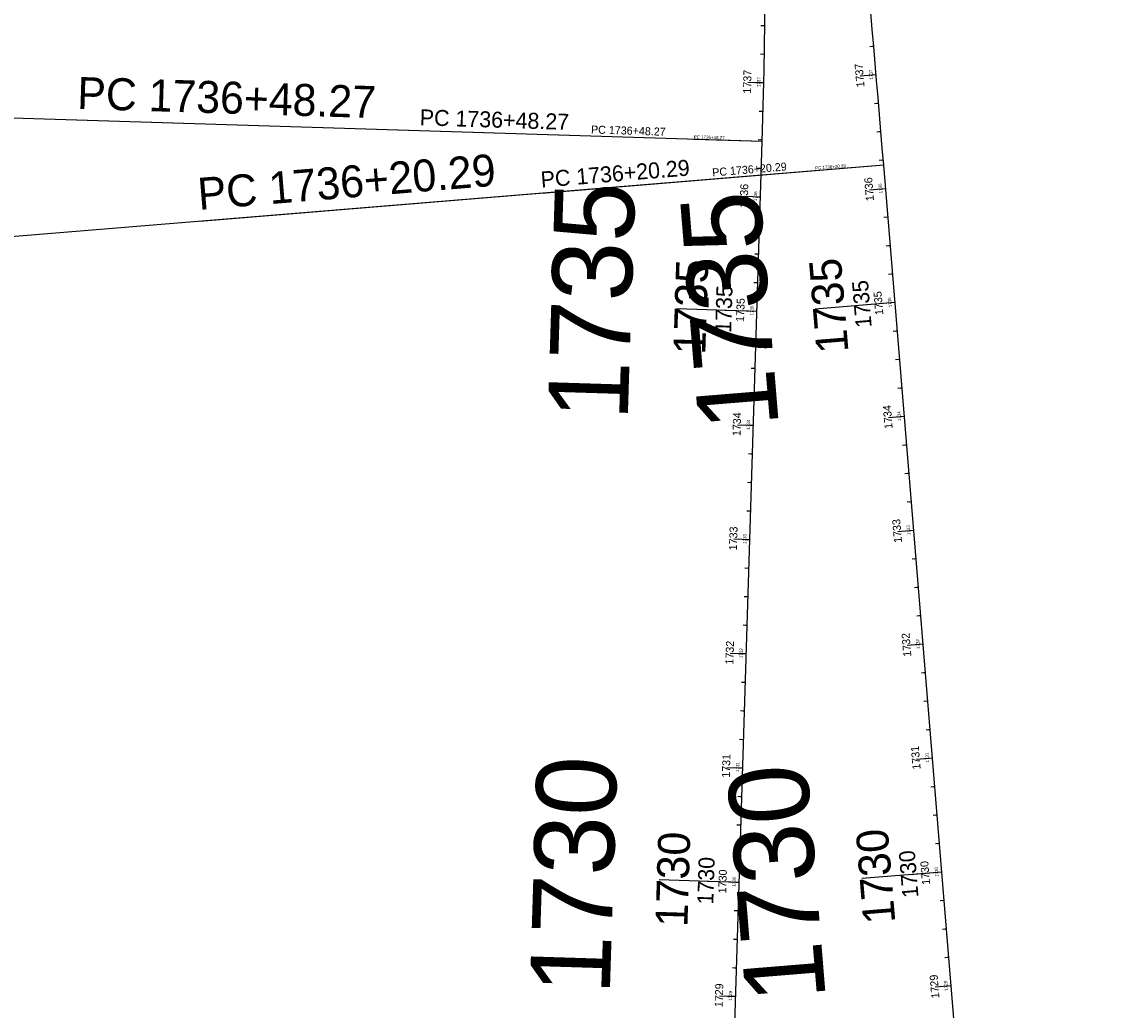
# Model space of a CAD drawing. Extents: x 353835 to 363333, y 126218 to 205387.
# Drawn here: x 360814 to 361763, y 132088 to 132953 of the extents above; entities that cross this region are included whole.
import ezdxf

# ---------------------------------------------------------------- set-up
doc = ezdxf.new("R2010")
doc.units = 0
for name, color, linetype in [('P_ALI_100_PIData', 7, 'Continuous'), ('P_ALI_100_Sta', 7, 'Continuous'), ('P_ALI_100_Tic', 7, 'Continuous'), ('P_ALI_20', 7, 'Continuous'), ('P_ALI_200_PIData', 7, 'Continuous'), ('P_ALI_200_Sta', 7, 'Continuous'), ('P_ALI_200_Tic', 7, 'Continuous'), ('P_ALI_20_PIData', 7, 'Continuous'), ('P_ALI_20_Sta', 7, 'Continuous'), ('P_ALI_20_Tic', 7, 'Continuous'), ('P_ALI_500_PIData', 7, 'Continuous'), ('P_ALI_500_Sta', 7, 'Continuous'), ('P_ALI_50_PIData', 7, 'Continuous'), ('P_ALI_50_Sta', 7, 'Continuous'), ('P_ALI_50_Tic', 7, 'Continuous')]:
    doc.layers.add(name, color=color, linetype=linetype)

msp = doc.modelspace()

# ---------------------------------------------------------------- linework, layer by layer
for points in [[(361561.59, 132906.59), (361561.61, 132906.59)], [(361569.89, 132806.93), (361569.91, 132806.93)], [(361586.24, 132607.6), (361586.26, 132607.6)], [(361594.42, 132507.94), (361594.44, 132507.94)], [(361602.59, 132408.27), (361602.61, 132408.27)], [(361610.77, 132308.61), (361610.79, 132308.61)], [(361627.12, 132109.28), (361627.14, 132109.28)]]:
    msp.add_lwpolyline(points)
at = {"layer": 'P_ALI_100_PIData'}
for points in [[(361462, 132847.85), (361162.15, 132857.21)], [(361462, 132847.85), (361402.03, 132849.72)], [(361568.24, 132827.16), (361269.24, 132802.63)], [(361568.24, 132827.16), (361508.44, 132822.25)]]:
    msp.add_lwpolyline(points, dxfattribs=at)
at = {"layer": 'P_ALI_100_Tic'}
for points in [[(361456.39, 132899.72), (361463.39, 132899.56)], [(361554.62, 132905.99), (361561.6, 132906.59)], [(361562.92, 132806.36), (361569.9, 132806.93)], [(361453.5, 132799.82), (361460.5, 132799.6)], [(361387.41, 132701.83), (361457.38, 132699.65)], [(361443.39, 132700.09), (361457.38, 132699.65)], [(361508.31, 132701.54), (361578.07, 132707.27)], [(361564.12, 132706.12), (361578.07, 132707.27)], [(361579.27, 132607.03), (361586.25, 132607.6)], [(361447.26, 132599.92), (361454.26, 132599.7)], [(361587.45, 132507.36), (361594.43, 132507.94)], [(361444.14, 132499.97), (361451.14, 132499.75)], [(361595.63, 132407.7), (361602.6, 132408.27)], [(361441.02, 132400.01), (361448.02, 132399.8)], [(361603.8, 132308.03), (361610.78, 132308.61)], [(361437.9, 132300.06), (361444.9, 132299.84)], [(361549.19, 132203.22), (361618.95, 132208.94)], [(361605, 132207.8), (361618.95, 132208.94)], [(361371.81, 132202.08), (361441.78, 132199.89)], [(361427.79, 132200.33), (361441.78, 132199.89)], [(361620.15, 132108.7), (361627.13, 132109.28)], [(361431.66, 132100.16), (361438.66, 132099.94)]]:
    msp.add_lwpolyline(points, dxfattribs=at)
at = {"layer": 'P_ALI_20'}
for p, q in [((361371.19, 129938.32), (361462, 132847.85)), ((361762.92, 130454.08), (361568.24, 132827.16))]:
    msp.add_line(p, q, dxfattribs=at)
for centre, radius, start, end in [((355564.88, 133031.92), 5900, 358.212155, 4.675416), ((336651.94, 130783.14), 25000, 4.689776, 5.78337)]:
    msp.add_arc(centre, radius, start, end, dxfattribs=at)
at = {"layer": 'P_ALI_200_PIData'}
for points in [[(361462, 132847.85), (360862.3, 132866.57)], [(361568.24, 132827.16), (360970.25, 132778.1)]]:
    msp.add_lwpolyline(points, dxfattribs=at)
at = {"layer": 'P_ALI_200_Tic'}
for points in [[(361449.4, 132899.87), (361463.39, 132899.56)], [(361547.65, 132905.4), (361561.6, 132906.59)], [(361555.94, 132805.79), (361569.9, 132806.93)], [(361446.51, 132800.04), (361460.5, 132799.6)], [(361429.39, 132700.52), (361457.38, 132699.65)], [(361550.17, 132704.98), (361578.07, 132707.27)], [(361572.3, 132606.46), (361586.25, 132607.6)], [(361440.27, 132600.14), (361454.26, 132599.7)], [(361437.15, 132500.18), (361451.14, 132499.75)], [(361580.47, 132506.79), (361594.43, 132507.94)], [(361588.65, 132407.13), (361602.6, 132408.27)], [(361434.03, 132400.23), (361448.02, 132399.8)], [(361596.83, 132307.46), (361610.78, 132308.61)], [(361430.91, 132300.28), (361444.9, 132299.84)], [(361591.05, 132206.65), (361618.95, 132208.94)], [(361413.79, 132200.77), (361441.78, 132199.89)], [(361613.18, 132108.13), (361627.13, 132109.28)], [(361424.67, 132100.38), (361438.66, 132099.94)]]:
    msp.add_lwpolyline(points, dxfattribs=at)
at = {"layer": 'P_ALI_20_Tic'}
for points in [[(361462.9, 132949.57), (361464.3, 132949.55)], [(361558.06, 132931.38), (361559.46, 132931.5)], [(361462.5, 132924.58), (361463.9, 132924.55)], [(361460.59, 132899.62), (361463.39, 132899.56)], [(361558.81, 132906.35), (361561.6, 132906.59)], [(361562.31, 132881.56), (361563.71, 132881.68)], [(361461.38, 132874.6), (361462.78, 132874.57)], [(361564.4, 132856.65), (361565.79, 132856.76)], [(361460.66, 132849.62), (361462.06, 132849.58)], [(361459.88, 132824.63), (361461.28, 132824.59)], [(361566.46, 132831.73), (361567.85, 132831.85)], [(361567.11, 132806.7), (361569.9, 132806.93)], [(361457.7, 132799.69), (361460.5, 132799.6)], [(361570.55, 132781.9), (361571.94, 132782.02)], [(361458.32, 132774.66), (361459.72, 132774.61)], [(361572.59, 132756.99), (361573.99, 132757.1)], [(361457.54, 132749.67), (361458.94, 132749.63)], [(361574.63, 132732.07), (361576.03, 132732.18)], [(361456.76, 132724.68), (361458.16, 132724.64)], [(361454.58, 132699.74), (361457.38, 132699.65)], [(361575.28, 132707.04), (361578.07, 132707.27)], [(361578.72, 132682.24), (361580.12, 132682.35)], [(361455.2, 132674.71), (361456.6, 132674.66)], [(361580.77, 132657.32), (361582.16, 132657.43)], [(361454.42, 132649.72), (361455.82, 132649.67)], [(361453.64, 132624.73), (361455.04, 132624.69)], [(361582.81, 132632.4), (361584.21, 132632.52)], [(361583.46, 132607.37), (361586.25, 132607.6)], [(361451.46, 132599.79), (361454.26, 132599.7)], [(361586.9, 132582.57), (361588.29, 132582.69)], [(361452.08, 132574.75), (361453.48, 132574.71)], [(361588.94, 132557.66), (361590.34, 132557.77)], [(361451.3, 132549.77), (361452.7, 132549.72)], [(361590.99, 132532.74), (361592.38, 132532.85)], [(361450.52, 132524.78), (361451.92, 132524.74)], [(361591.64, 132507.71), (361594.43, 132507.94)], [(361448.34, 132499.83), (361451.14, 132499.75)], [(361595.07, 132482.91), (361596.47, 132483.02)], [(361448.96, 132474.8), (361450.36, 132474.76)], [(361597.12, 132457.99), (361598.51, 132458.1)], [(361448.18, 132449.82), (361449.58, 132449.77)], [(361447.4, 132424.83), (361448.8, 132424.78)], [(361599.16, 132433.07), (361600.56, 132433.19)], [(361599.81, 132408.04), (361602.6, 132408.27)], [(361445.22, 132399.88), (361448.02, 132399.8)], [(361603.25, 132383.24), (361604.65, 132383.36)], [(361445.84, 132374.85), (361447.24, 132374.81)], [(361605.3, 132358.32), (361606.69, 132358.44)], [(361445.06, 132349.86), (361446.46, 132349.82)], [(361607.34, 132333.41), (361608.73, 132333.52)], [(361444.28, 132324.88), (361445.68, 132324.83)], [(361607.99, 132308.38), (361610.78, 132308.61)], [(361442.1, 132299.93), (361444.9, 132299.84)], [(361611.43, 132283.58), (361612.82, 132283.69)], [(361442.72, 132274.9), (361444.12, 132274.86)], [(361613.47, 132258.66), (361614.87, 132258.77)], [(361441.94, 132249.91), (361443.34, 132249.87)], [(361441.16, 132224.92), (361442.56, 132224.88)], [(361615.52, 132233.74), (361616.91, 132233.86)], [(361616.16, 132208.71), (361618.95, 132208.94)], [(361438.98, 132199.98), (361441.78, 132199.89)], [(361619.6, 132183.91), (361621, 132184.03)], [(361439.6, 132174.95), (361441, 132174.91)], [(361621.65, 132158.99), (361623.04, 132159.11)], [(361438.82, 132149.96), (361440.22, 132149.92)], [(361623.69, 132134.08), (361625.09, 132134.19)], [(361438.04, 132124.97), (361439.44, 132124.93)], [(361624.34, 132109.05), (361627.13, 132109.28)], [(361435.86, 132100.03), (361438.66, 132099.94)]]:
    msp.add_lwpolyline(points, dxfattribs=at)
at = {"layer": 'P_ALI_500_PIData'}
for points in [[(361462, 132847.85), (359962.74, 132894.64)], [(361568.24, 132827.16), (360073.26, 132704.51)]]:
    msp.add_lwpolyline(points, dxfattribs=at)
at = {"layer": 'P_ALI_50_PIData'}
for points in [[(361462, 132847.85), (361312.08, 132852.53)], [(361462, 132847.85), (361312.08, 132852.53)], [(361568.24, 132827.16), (361418.74, 132814.89)]]:
    msp.add_lwpolyline(points, dxfattribs=at)
at = {"layer": 'P_ALI_50_Tic'}
for points in [[(361460.8, 132949.6), (361464.3, 132949.55)], [(361460.8, 132949.6), (361464.3, 132949.55)], [(361555.97, 132931.2), (361559.46, 132931.5)], [(361460.4, 132924.62), (361463.9, 132924.55)], [(361460.4, 132924.62), (361463.9, 132924.55)], [(361456.39, 132899.72), (361463.39, 132899.56)], [(361456.39, 132899.72), (361463.39, 132899.56)], [(361554.62, 132905.99), (361561.6, 132906.59)], [(361560.22, 132881.38), (361563.71, 132881.68)], [(361459.28, 132874.66), (361462.78, 132874.57)], [(361459.28, 132874.66), (361462.78, 132874.57)], [(361562.3, 132856.47), (361565.79, 132856.76)], [(361458.56, 132849.69), (361462.06, 132849.58)], [(361458.56, 132849.69), (361462.06, 132849.58)], [(361457.78, 132824.7), (361461.28, 132824.59)], [(361457.78, 132824.7), (361461.28, 132824.59)], [(361564.37, 132831.56), (361567.85, 132831.85)], [(361562.92, 132806.36), (361569.9, 132806.93)], [(361453.5, 132799.82), (361460.5, 132799.6)], [(361453.5, 132799.82), (361460.5, 132799.6)], [(361568.45, 132781.73), (361571.94, 132782.02)], [(361456.22, 132774.72), (361459.72, 132774.61)], [(361456.22, 132774.72), (361459.72, 132774.61)], [(361570.5, 132756.81), (361573.99, 132757.1)], [(361455.44, 132749.73), (361458.94, 132749.63)], [(361455.44, 132749.73), (361458.94, 132749.63)], [(361572.54, 132731.9), (361576.03, 132732.18)], [(361454.66, 132724.75), (361458.16, 132724.64)], [(361454.66, 132724.75), (361458.16, 132724.64)], [(361450.38, 132699.87), (361457.38, 132699.65)], [(361450.38, 132699.87), (361457.38, 132699.65)], [(361571.1, 132706.7), (361578.07, 132707.27)], [(361576.63, 132682.07), (361580.12, 132682.35)], [(361453.1, 132674.77), (361456.6, 132674.66)], [(361453.1, 132674.77), (361456.6, 132674.66)], [(361578.67, 132657.15), (361582.16, 132657.43)], [(361452.32, 132649.78), (361455.82, 132649.67)], [(361452.32, 132649.78), (361455.82, 132649.67)], [(361451.54, 132624.8), (361455.04, 132624.69)], [(361451.54, 132624.8), (361455.04, 132624.69)], [(361580.72, 132632.23), (361584.21, 132632.52)], [(361579.27, 132607.03), (361586.25, 132607.6)], [(361447.26, 132599.92), (361454.26, 132599.7)], [(361447.26, 132599.92), (361454.26, 132599.7)], [(361584.81, 132582.4), (361588.29, 132582.69)], [(361449.98, 132574.82), (361453.48, 132574.71)], [(361449.98, 132574.82), (361453.48, 132574.71)], [(361586.85, 132557.48), (361590.34, 132557.77)], [(361449.2, 132549.83), (361452.7, 132549.72)], [(361449.2, 132549.83), (361452.7, 132549.72)], [(361588.89, 132532.57), (361592.38, 132532.85)], [(361448.42, 132524.84), (361451.92, 132524.74)], [(361448.42, 132524.84), (361451.92, 132524.74)], [(361587.45, 132507.36), (361594.43, 132507.94)], [(361444.14, 132499.97), (361451.14, 132499.75)], [(361444.14, 132499.97), (361451.14, 132499.75)], [(361592.98, 132482.73), (361596.47, 132483.02)], [(361446.86, 132474.87), (361450.36, 132474.76)], [(361446.86, 132474.87), (361450.36, 132474.76)], [(361595.03, 132457.82), (361598.51, 132458.1)], [(361446.08, 132449.88), (361449.58, 132449.77)], [(361446.08, 132449.88), (361449.58, 132449.77)], [(361445.3, 132424.89), (361448.8, 132424.78)], [(361445.3, 132424.89), (361448.8, 132424.78)], [(361597.07, 132432.9), (361600.56, 132433.19)], [(361595.63, 132407.7), (361602.6, 132408.27)], [(361441.02, 132400.01), (361448.02, 132399.8)], [(361441.02, 132400.01), (361448.02, 132399.8)], [(361601.16, 132383.07), (361604.65, 132383.36)], [(361443.74, 132374.92), (361447.24, 132374.81)], [(361443.74, 132374.92), (361447.24, 132374.81)], [(361603.2, 132358.15), (361606.69, 132358.44)], [(361442.96, 132349.93), (361446.46, 132349.82)], [(361442.96, 132349.93), (361446.46, 132349.82)], [(361605.25, 132333.24), (361608.73, 132333.52)], [(361442.18, 132324.94), (361445.68, 132324.83)], [(361442.18, 132324.94), (361445.68, 132324.83)], [(361603.8, 132308.03), (361610.78, 132308.61)], [(361437.9, 132300.06), (361444.9, 132299.84)], [(361437.9, 132300.06), (361444.9, 132299.84)], [(361609.33, 132283.4), (361612.82, 132283.69)], [(361440.62, 132274.97), (361444.12, 132274.86)], [(361440.62, 132274.97), (361444.12, 132274.86)], [(361611.38, 132258.49), (361614.87, 132258.77)], [(361439.84, 132249.98), (361443.34, 132249.87)], [(361439.84, 132249.98), (361443.34, 132249.87)], [(361439.06, 132224.99), (361442.56, 132224.88)], [(361439.06, 132224.99), (361442.56, 132224.88)], [(361613.42, 132233.57), (361616.91, 132233.86)], [(361611.98, 132208.37), (361618.95, 132208.94)], [(361434.78, 132200.11), (361441.78, 132199.89)], [(361434.78, 132200.11), (361441.78, 132199.89)], [(361617.51, 132183.74), (361621, 132184.03)], [(361437.5, 132175.01), (361441, 132174.91)], [(361437.5, 132175.01), (361441, 132174.91)], [(361619.55, 132158.82), (361623.04, 132159.11)], [(361436.72, 132150.03), (361440.22, 132149.92)], [(361436.72, 132150.03), (361440.22, 132149.92)], [(361621.6, 132133.91), (361625.09, 132134.19)], [(361435.94, 132125.04), (361439.44, 132124.93)], [(361435.94, 132125.04), (361439.44, 132124.93)], [(361620.15, 132108.7), (361627.13, 132109.28)], [(361431.66, 132100.16), (361438.66, 132099.94)], [(361431.66, 132100.16), (361438.66, 132099.94)]]:
    msp.add_lwpolyline(points, dxfattribs=at)

# ---------------------------------------------------------------- texts
at = {"layer": 'P_ALI_100_PIData'}
for s, rotation, p in [('PC 1736+48.27', 358.21215, (361162.31, 132862.2)), ('PC 1736+20.29', 4.68978, (361268.83, 132807.61))]:
    msp.add_text(s, height=14, rotation=rotation, dxfattribs=at).set_placement(p)
at = {"layer": 'P_ALI_100_Sta'}
for s, rotation, p in [('1735', 88.21215, (361434.77, 132680.39)), ('1735', 94.68978, (361557.78, 132685.58)), ('1730', 94.68978, (361598.7, 132186.71)), ('1730', 88.21215, (361419.15, 132180.09))]:
    msp.add_text(s, height=14, rotation=rotation, dxfattribs=at).set_placement(p)
at = {"layer": 'P_ALI_200_PIData'}
for s, rotation, p in [('PC 1736+48.27', 358.21215, (360862.61, 132876.56)), ('PC 1736+20.29', 4.68978, (360969.43, 132788.07))]:
    msp.add_text(s, height=28, rotation=rotation, dxfattribs=at).set_placement(p)
at = {"layer": 'P_ALI_200_Sta'}
for s, rotation, p in [('1735', 88.21215, (361412.16, 132661.14)), ('1735', 94.68978, (361537.48, 132663.9)), ('1730', 94.68978, (361578.45, 132164.47)), ('1730', 88.21215, (361396.52, 132160.28))]:
    msp.add_text(s, height=28, rotation=rotation, dxfattribs=at).set_placement(p)
at = {"layer": 'P_ALI_20_PIData'}
for s, rotation, p in [('PC 1736+48.27', 358.21215, (361402.07, 132850.72)), ('PC 1736+20.29', 4.68978, (361508.36, 132823.25)), ('PC 1736+20.29', 4.68978, (361508.36, 132823.25))]:
    msp.add_text(s, height=2.8, rotation=rotation, dxfattribs=at).set_placement(p)
at = {"layer": 'P_ALI_20_Sta'}
for s, rotation, p in [('1737', 94.87246, (361558.87, 132902.35)), ('1737', 88.71453, (361460.22, 132895.64)), ('1736', 88.21215, (361457.3, 132795.72)), ('1736', 94.68978, (361567.15, 132802.71)), ('1735', 94.68978, (361575.33, 132703.04)), ('1735', 88.21215, (361454.18, 132695.76)), ('1734', 94.68978, (361583.51, 132603.37)), ('1734', 88.21215, (361451.06, 132595.81)), ('1733', 94.68978, (361591.68, 132503.71)), ('1733', 88.21215, (361447.94, 132495.85)), ('1732', 94.68978, (361599.86, 132404.04)), ('1732', 88.21215, (361444.82, 132395.9)), ('1731', 94.68978, (361608.01, 132304.73)), ('1731', 88.21215, (361441.71, 132296.3)), ('1730', 94.68978, (361616.22, 132204.6)), ('1730', 88.21215, (361438.57, 132195.89)), ('1729', 94.68978, (361624.39, 132105.05)), ('1729', 88.21215, (361435.46, 132096.05))]:
    msp.add_text(s, height=2.8, rotation=rotation, dxfattribs=at).set_placement(p)
at = {"layer": 'P_ALI_500_Sta'}
for s, rotation, p in [('1735', 88.21215, (361344.32, 132603.37)), ('1735', 94.68978, (361476.6, 132598.84)), ('1730', 88.21215, (361328.63, 132100.86)), ('1730', 94.68978, (361517.7, 132097.77))]:
    msp.add_text(s, height=70, rotation=rotation, dxfattribs=at).set_placement(p)
at = {"layer": 'P_ALI_50_PIData'}
for s, rotation, p in [('PC 1736+48.27', 358.21215, (361312.16, 132855.03)), ('PC 1736+48.27', 358.21215, (361312.16, 132855.03)), ('PC 1736+20.29', 4.68978, (361418.54, 132817.38)), ('PC 1736+20.29', 4.68978, (361418.54, 132817.38))]:
    msp.add_text(s, height=7, rotation=rotation, dxfattribs=at).set_placement(p)
at = {"layer": 'P_ALI_50_Sta'}
for s, rotation, p in [('1737', 88.71453, (361452.17, 132889.83)), ('1737', 88.71453, (361452.17, 132889.83)), ('1737', 94.87246, (361551.48, 132895.71)), ('1736', 94.68978, (361559.75, 132796.12)), ('1736', 88.21215, (361449.19, 132790)), ('1736', 88.21215, (361449.19, 132790)), ('1735', 88.21215, (361446.07, 132690.02)), ('1735', 88.21215, (361446.07, 132690.02)), ('1735', 94.68978, (361567.93, 132696.43)), ('1734', 94.68978, (361576.1, 132596.76)), ('1734', 88.21215, (361442.95, 132590.07)), ('1734', 88.21215, (361442.95, 132590.07)), ('1733', 88.21215, (361439.83, 132490.12)), ('1733', 88.21215, (361439.83, 132490.12)), ('1733', 94.68978, (361584.28, 132497.09)), ('1732', 94.68978, (361592.45, 132397.43)), ('1732', 88.21215, (361436.71, 132390.17)), ('1732', 88.21215, (361436.71, 132390.17)), ('1731', 88.21215, (361433.62, 132291.1)), ('1731', 88.21215, (361433.62, 132291.1)), ('1731', 94.68978, (361600.56, 132298.64)), ('1730', 94.68978, (361608.83, 132197.82)), ('1730', 88.21215, (361430.47, 132189.99)), ('1730', 88.21215, (361430.47, 132189.99)), ('1729', 94.68978, (361616.98, 132098.43)), ('1729', 88.21215, (361427.35, 132090.31)), ('1729', 88.21215, (361427.35, 132090.31))]:
    msp.add_text(s, height=7, rotation=rotation, dxfattribs=at).set_placement(p)

doc.saveas('drawing.dxf')
